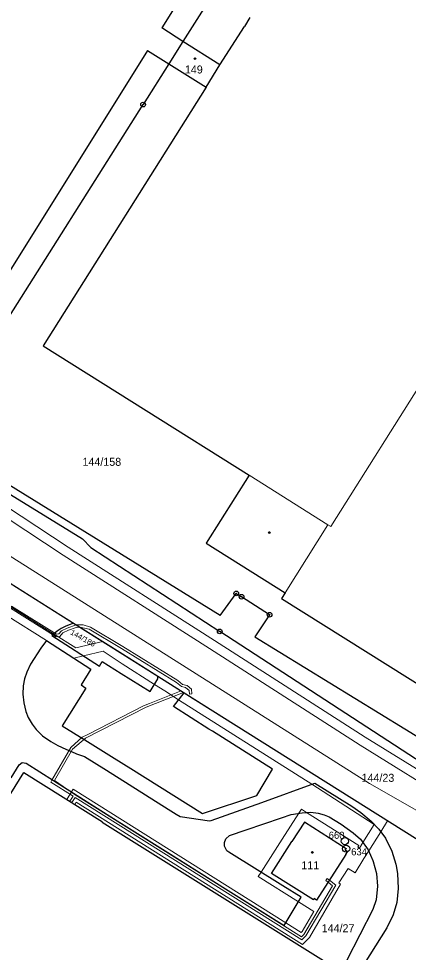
# Model space of a CAD drawing. Extents: x -645290 to -643454, y -1064771 to -1062356.
# Drawn here: x -644155.9 to -644073.2, y -1063226 to -1063027.7 of the extents above; entities that cross this region are included whole.
import ezdxf
from ezdxf.enums import TextEntityAlignment as Align

# ---------------------------------------------------------------- set-up
doc = ezdxf.new("R2010")
doc.units = 0
doc.header["$LTSCALE"] = 0.68
for name, color, linetype, lineweight in [('1', 7, 'Continuous', 25), ('13', 7, 'Continuous', 13), ('4', 7, 'Continuous', 13), ('5', 7, 'Continuous', 25), ('8', 7, 'Continuous', 25)]:
    doc.layers.add(name, color=color, linetype=linetype, lineweight=lineweight)
doc.layers.add('2', color=7, linetype='Continuous')

msp = doc.modelspace()

# ---------------------------------------------------------------- linework, layer by layer
at = {"layer": '1'}
for p, q in [((-644076.89, -1062962.59), (-644121.06, -1063032.53)), ((-644110.5, -1063005.53), (-644125.57, -1063029.65)), ((-644106.84, -1063027.43), (-644108.03, -1063029.33)), ((-644121.06, -1063032.53), (-644125.57, -1063029.65)), ((-644113.2, -1063037.54), (-644108.03, -1063029.33)), ((-644121.06, -1063032.53), (-644124.08, -1063037.31)), ((-644113.2, -1063037.54), (-644121.06, -1063032.53)), ((-644128.6, -1063034.49), (-644158.52, -1063082.37)), ((-644128.6, -1063034.49), (-644124.08, -1063037.31)), ((-644124.08, -1063037.31), (-644129.53, -1063045.94)), ((-644124.08, -1063037.31), (-644116.16, -1063042.25)), ((-644116.16, -1063042.25), (-644113.2, -1063037.54)), ((-644116.16, -1063042.25), (-644150.74, -1063097.22)), ((-644173.98, -1063116.33), (-644129.53, -1063045.94)), ((-644113.13, -1063154.51), (-644169.04, -1063119.98)), ((-644169.78, -1063121.34), (-644142.4, -1063138.22)), ((-644142.4, -1063138.22), (-644140.61, -1063140.05)), ((-644140.61, -1063140.05), (-644113.26, -1063157.87)), ((-644160.63, -1063145.86), (-644144.31, -1063156.13)), ((-644113.13, -1063154.51), (-644109.74, -1063149.81)), ((-644109.74, -1063149.81), (-644108.62, -1063150.52)), ((-644102.67, -1063154.33), (-644108.62, -1063150.52)), ((-644099.36, -1063149.67), (-644100.11, -1063150.87)), ((-644100.11, -1063150.87), (-644046.66, -1063184.45)), ((-644102.67, -1063154.33), (-644105.82, -1063159.04)), ((-644145.05, -1063156.38), (-644145.97, -1063156.79)), ((-644144.31, -1063156.13), (-644145.05, -1063156.38)), ((-644144.31, -1063156.13), (-644126.38, -1063167.41)), ((-644147.77, -1063157.81), (-644148.94, -1063158.73)), ((-644148.94, -1063158.73), (-644138.78, -1063165.26)), ((-644146.91, -1063157.25), (-644147.77, -1063157.81)), ((-644145.97, -1063156.79), (-644146.91, -1063157.25)), ((-644060.32, -1063192.37), (-644113.26, -1063157.87)), ((-644150.07, -1063159.78), (-644151.27, -1063161.42)), ((-644150.07, -1063159.78), (-644140.65, -1063165.92)), ((-644105.82, -1063159.04), (-644064.47, -1063184.41)), ((-644151.27, -1063161.42), (-644153.44, -1063164.82)), ((-644138.78, -1063165.26), (-644138.21, -1063164.27)), ((-644138.21, -1063164.27), (-644134.22, -1063166.79)), ((-644154.2, -1063166.54), (-644154.68, -1063167.92)), ((-644153.44, -1063164.82), (-644154.2, -1063166.54)), ((-644140.65, -1063165.92), (-644142.69, -1063169.25)), ((-644154.68, -1063167.92), (-644154.97, -1063169.45)), ((-644134.22, -1063166.79), (-644128.06, -1063170.66)), ((-644128.06, -1063170.66), (-644126.4, -1063167.98)), ((-644126.4, -1063167.98), (-644126.38, -1063167.41)), ((-644126.38, -1063167.41), (-644120.82, -1063170.91)), ((-644154.97, -1063169.45), (-644155.04, -1063171.22)), ((-644141.7, -1063169.9), (-644146.71, -1063177.9)), ((-644142.69, -1063169.25), (-644141.7, -1063169.9)), ((-644155.04, -1063171.22), (-644154.89, -1063173.03)), ((-644123.09, -1063173.8), (-644120.82, -1063170.91)), ((-644120.82, -1063170.91), (-644065.09, -1063205.97)), ((-644154.89, -1063173.03), (-644154.45, -1063174.88)), ((-644115.55, -1063178.61), (-644123.09, -1063173.8)), ((-644154.45, -1063174.88), (-644153.94, -1063176.19)), ((-644153.94, -1063176.19), (-644153.12, -1063177.57)), ((-644153.12, -1063177.57), (-644152.23, -1063178.73)), ((-644146.71, -1063177.9), (-644141.93, -1063180.89)), ((-644152.23, -1063178.73), (-644150.9, -1063180.05)), ((-644150.9, -1063180.05), (-644149.15, -1063181.25)), ((-644114.81, -1063179.08), (-644115.55, -1063178.61)), ((-644102.02, -1063187.13), (-644114.81, -1063179.08)), ((-644149.15, -1063181.25), (-644147.61, -1063182.13)), ((-644147.61, -1063182.13), (-644145.95, -1063182.89)), ((-644141.93, -1063180.89), (-644135.7, -1063184.78)), ((-644145.95, -1063182.89), (-644143.95, -1063183.74)), ((-644143.95, -1063183.74), (-644143.64, -1063183.85)), ((-644143.64, -1063183.85), (-644141.99, -1063184.44)), ((-644141.99, -1063184.44), (-644137.33, -1063187.38)), ((-644157.55, -1063188.97), (-644155.82, -1063186.19)), ((-644155.82, -1063186.19), (-644155.18, -1063185.71)), ((-644155.18, -1063185.71), (-644154.37, -1063185.88)), ((-644154.37, -1063185.88), (-644148.59, -1063189.53)), ((-644135.7, -1063184.78), (-644132.11, -1063187.02)), ((-644137.33, -1063187.38), (-644124.21, -1063195.62)), ((-644132.11, -1063187.02), (-644116.95, -1063196.54)), ((-644105.41, -1063192.72), (-644102.02, -1063187.13)), ((-644148.59, -1063189.53), (-644135.02, -1063198.09)), ((-644104.33, -1063194.19), (-644093.08, -1063190.1)), ((-644093.08, -1063190.1), (-644085.22, -1063194.99)), ((-644116.95, -1063196.54), (-644105.41, -1063192.72)), ((-644115.07, -1063198.03), (-644104.33, -1063194.19)), ((-644124.21, -1063195.62), (-644122.51, -1063196.69)), ((-644098.08, -1063196.75), (-644095.78, -1063196.43)), ((-644095.78, -1063196.43), (-644093.92, -1063196.26)), ((-644093.92, -1063196.26), (-644092.34, -1063196.47)), ((-644085.22, -1063194.99), (-644083.3, -1063196.33)), ((-644083.3, -1063196.33), (-644081.11, -1063198.17)), ((-644135.02, -1063198.09), (-644133.57, -1063199.02)), ((-644122.51, -1063196.69), (-644121.63, -1063197.19)), ((-644121.63, -1063197.19), (-644115.41, -1063198.15)), ((-644115.41, -1063198.15), (-644115.07, -1063198.03)), ((-644107.61, -1063200), (-644100.17, -1063197.47)), ((-644100.17, -1063197.47), (-644098.08, -1063196.75)), ((-644095.29, -1063198.4), (-644097.95, -1063202.54)), ((-644086.41, -1063204.03), (-644095.29, -1063198.4)), ((-644092.34, -1063196.47), (-644091.07, -1063196.82)), ((-644091.07, -1063196.82), (-644090.03, -1063197.3)), ((-644090.03, -1063197.3), (-644087.45, -1063198.84)), ((-644081.11, -1063198.17), (-644079.47, -1063199.88)), ((-644133.57, -1063199.02), (-644123.74, -1063205.22)), ((-644111.18, -1063201.21), (-644107.61, -1063200)), ((-644087.45, -1063198.84), (-644084.94, -1063200.64)), ((-644112.25, -1063202.69), (-644111.93, -1063201.93)), ((-644111.93, -1063201.93), (-644111.18, -1063201.21)), ((-644084.94, -1063200.64), (-644083.35, -1063201.99)), ((-644083.35, -1063201.99), (-644081.71, -1063204.29)), ((-644112.21, -1063203.52), (-644112.25, -1063202.69)), ((-644111.73, -1063204.47), (-644112.21, -1063203.52)), ((-644102.29, -1063209.3), (-644097.95, -1063202.54)), ((-644086.61, -1063204.37), (-644086.41, -1063204.03)), ((-644086.11, -1063204.69), (-644086.61, -1063204.37)), ((-644081.71, -1063204.29), (-644080.75, -1063206.55)), ((-644123.74, -1063205.22), (-644112, -1063212.53)), ((-644111.35, -1063204.79), (-644111.73, -1063204.47)), ((-644086.47, -1063205.25), (-644092.69, -1063214.95)), ((-644086.47, -1063205.25), (-644086.11, -1063204.69)), ((-644076.71, -1063204.58), (-644075.88, -1063207.31)), ((-644080.75, -1063206.55), (-644080.68, -1063206.73)), ((-644080.68, -1063206.73), (-644079.98, -1063209.33)), ((-644075.88, -1063207.31), (-644075.81, -1063207.67)), ((-644075.81, -1063207.67), (-644075.5, -1063209.3)), ((-644093.37, -1063214.92), (-644102.29, -1063209.3)), ((-644079.98, -1063209.33), (-644079.75, -1063212.02)), ((-644075.5, -1063209.3), (-644075.34, -1063212.51)), ((-644079.75, -1063212.02), (-644080.03, -1063214.87)), ((-644112, -1063212.53), (-644099.57, -1063220.34)), ((-644075.34, -1063212.51), (-644075.65, -1063215.43)), ((-644099.57, -1063220.34), (-644095.93, -1063214.32)), ((-644093.19, -1063214.63), (-644093.37, -1063214.92)), ((-644092.69, -1063214.95), (-644093.19, -1063214.63)), ((-644080.03, -1063214.87), (-644080.77, -1063216.97)), ((-644075.65, -1063215.43), (-644076.4, -1063218.12)), ((-644080.77, -1063216.97), (-644086.24, -1063227.71)), ((-644076.4, -1063218.12), (-644077.74, -1063220.84)), ((-644077.74, -1063220.84), (-644083.77, -1063230.42))]:
    msp.add_line(p, q, dxfattribs=at)
for points in [[(-644150.74, -1063097.22), (-644107.04, -1063124.68), (-644116.14, -1063139.12), (-644099.36, -1063149.67)], [(-644162.87, -1063200.63), (-644154.86, -1063187.84), (-644138.14, -1063198.3), (-644138.19, -1063198.38), (-644088.93, -1063229.19), (-644197.53, -1063402.92), (-644246.76, -1063372.17), (-644246.82, -1063372.26), (-644263.58, -1063361.75), (-644255.56, -1063348.85)], [(-644079.47, -1063199.88), (-644078.07, -1063201.8), (-644076.71, -1063204.58)], [(-644095.93, -1063214.32), (-644099.83, -1063211.93), (-644111.35, -1063204.79)]]:
    msp.add_lwpolyline(points, dxfattribs=at)
at = {"layer": '13'}
for points in [[(-644175.47, -1063119.76), (-644177.34, -1063118.44), (-644175.73, -1063115.62), (-644177.14, -1063114.69), (-644177.4, -1063114.52), (-644180.02, -1063119.08), (-644176.52, -1063121.53), (-644166.59, -1063128.45), (-644146.52, -1063141.67), (-644115.44, -1063161.49), (-644083.43, -1063182.03), (-644063.09, -1063194.64), (-644060.39, -1063196.06), (-644060.35, -1063193.82), (-644062.09, -1063192.9), (-644082.37, -1063180.33), (-644114.36, -1063159.81), (-644145.44, -1063139.99), (-644165.45, -1063126.81)], [(-644157.44, -1063152.51), (-644157.71, -1063152.93), (-644148, -1063158.99), (-644147.24, -1063158.93), (-644146.57, -1063158.17), (-644145.34, -1063157.62), (-644143.71, -1063157.02), (-644142.93, -1063157), (-644143.73, -1063156.5), (-644145.62, -1063157.2), (-644146.89, -1063157.77), (-644147.44, -1063158.41), (-644147.92, -1063158.45)], [(-644142.93, -1063157), (-644140.95, -1063157.43), (-644134.1, -1063161.49), (-644122.46, -1063168.7), (-644121.39, -1063169.56), (-644120.51, -1063169.81), (-644119.74, -1063170.44), (-644119.69, -1063171.17), (-644119.19, -1063171.13), (-644119.26, -1063170.16), (-644120.19, -1063169.37), (-644121.13, -1063169.12), (-644122.14, -1063168.3), (-644133.84, -1063161.07), (-644140.71, -1063156.97), (-644142.25, -1063156.48), (-644143.73, -1063156.5)], [(-644090.25, -1063211.14), (-644089.28, -1063211.89), (-644095.39, -1063222.24), (-644095.88, -1063222.74), (-644143.94, -1063192.61), (-644148.37, -1063189.54), (-644144.49, -1063182.86), (-644141.74, -1063180.56), (-644128.91, -1063173.99), (-644120.96, -1063170.82), (-644121.48, -1063170.5), (-644128.17, -1063173.16), (-644129.44, -1063173.67), (-644141.29, -1063179.77), (-644142.44, -1063180.36), (-644144.87, -1063182.52), (-644148.93, -1063189.51), (-644149.15, -1063189.89), (-644144.41, -1063192.9), (-644145.06, -1063193.97), (-644144.64, -1063194.23), (-644143.99, -1063193.16), (-644095.84, -1063223.4), (-644094.99, -1063222.56), (-644088.58, -1063211.79), (-644089.98, -1063210.72), (-644090.45, -1063210.35), (-644090.72, -1063210.77)], [(-644095.29, -1063198.4), (-644086.41, -1063204.03), (-644086.61, -1063204.37), (-644086.11, -1063204.69), (-644086.47, -1063205.25), (-644092.69, -1063214.95), (-644093.19, -1063214.63), (-644093.37, -1063214.92), (-644102.29, -1063209.3), (-644097.95, -1063202.54)]]:
    msp.add_lwpolyline(points, close=True, dxfattribs=at)
for points in [[(-644061.99, -1063201.29), (-644081.47, -1063190.21), (-644180.21, -1063127.74), (-644182.72, -1063131.97), (-644168.06, -1063141.19), (-644155.36, -1063149.18), (-644133.92, -1063162.67), (-644122.95, -1063169.57), (-644065.09, -1063205.97)], [(-644158.64, -1063154.43), (-644150.07, -1063159.78), (-644144.24, -1063163.58), (-644142.17, -1063163.08), (-644138.04, -1063162.08), (-644134.01, -1063164.78), (-644127.12, -1063169.14), (-644124.93, -1063170.53), (-644121.99, -1063172.4), (-644093.7, -1063190.32), (-644080.44, -1063198.86), (-644082.85, -1063202.7), (-644083.61, -1063203.91), (-644083.91, -1063203.72), (-644083.71, -1063203.38), (-644094.81, -1063196.34), (-644095.9, -1063195.65), (-644096.46, -1063196.52), (-644099.98, -1063202.01), (-644104.49, -1063209.04), (-644105.06, -1063209.92), (-644096.52, -1063215.3), (-644093.28, -1063217.35), (-644095.77, -1063221.64), (-644095.98, -1063221.85), (-644099.24, -1063219.8), (-644144.36, -1063191.4), (-644144.72, -1063191.97), (-644145.71, -1063193.57), (-644144.01, -1063194.63), (-644143.72, -1063194.16), (-644095.7, -1063224.39), (-644094.17, -1063222.88), (-644087.61, -1063211.56), (-644087.97, -1063211.29), (-644086.01, -1063208.23), (-644084.53, -1063209.16), (-644082.63, -1063206.12), (-644081.62, -1063204.51), (-644079.07, -1063200.43), (-644077.61, -1063198.1), (-644120.82, -1063170.91), (-644122.95, -1063169.57), (-644126.38, -1063167.41), (-644133.92, -1063162.67), (-644138.1, -1063160.04), (-644143.82, -1063161.35), (-644148.53, -1063158.4), (-644157.58, -1063152.73)]]:
    msp.add_lwpolyline(points, dxfattribs=at)
at = {"layer": '4'}
for p, q in [((-644089.68, -1063135.58), (-644066.89, -1063099.35)), ((-644090.3, -1063135.2), (-644107.04, -1063124.68)), ((-644099.36, -1063149.67), (-644090.3, -1063135.2)), ((-644090.3, -1063135.2), (-644089.68, -1063135.58))]:
    msp.add_line(p, q, dxfattribs=at)
at = {"layer": '5'}
for centre in [(-644118.5068, -1063036.1792), (-644102.7268, -1063136.8692), (-644093.5868, -1063204.8292)]:
    msp.add_circle(centre, 0.175, dxfattribs=at)
at = {"layer": '8'}
for centre, radius in [((-644129.53, -1063045.9399), 0.5), ((-644129.53, -1063045.9399), 0.0303), ((-644109.74, -1063149.8099), 0.5), ((-644109.74, -1063149.8099), 0.0303), ((-644108.62, -1063150.5199), 0.5), ((-644108.62, -1063150.5199), 0.0303), ((-644102.67, -1063154.3299), 0.5), ((-644102.67, -1063154.3299), 0.0303), ((-644113.26, -1063157.8699), 0.5), ((-644113.26, -1063157.8699), 0.0303), ((-644086.69, -1063202.4298), 0.75), ((-644086.41, -1063204.0298), 0.75), ((-644086.69, -1063202.4298), 0.03), ((-644086.41, -1063204.0298), 0.03)]:
    msp.add_circle(centre, radius, dxfattribs=at)

# ---------------------------------------------------------------- texts
at = {"layer": '2'}
for s, p in [('149', (-644118.759, -1063039.344)), ('144/23', (-644079.66, -1063189.824)), ('111', (-644094.029, -1063208.415)), ('144/27', (-644088.13, -1063221.785))]:
    msp.add_text(s, height=1.7, dxfattribs=at).set_placement(p, align=Align.CENTER)
msp.add_text('144/158', height=1.7, dxfattribs=at).set_placement((-644142.4, -1063122.695))
at = {"layer": '2', "width": 1.05}
msp.add_text('144/186', height=1.139, rotation=331, dxfattribs=at).set_placement((-644145.108, -1063158.409))
at = {"layer": '8'}
for s, p in [('660', (-644090.115, -1063201.928)), ('634', (-644085.345, -1063205.443))]:
    msp.add_text(s, height=1.5, dxfattribs=at).set_placement(p)

doc.saveas('drawing.dxf')
